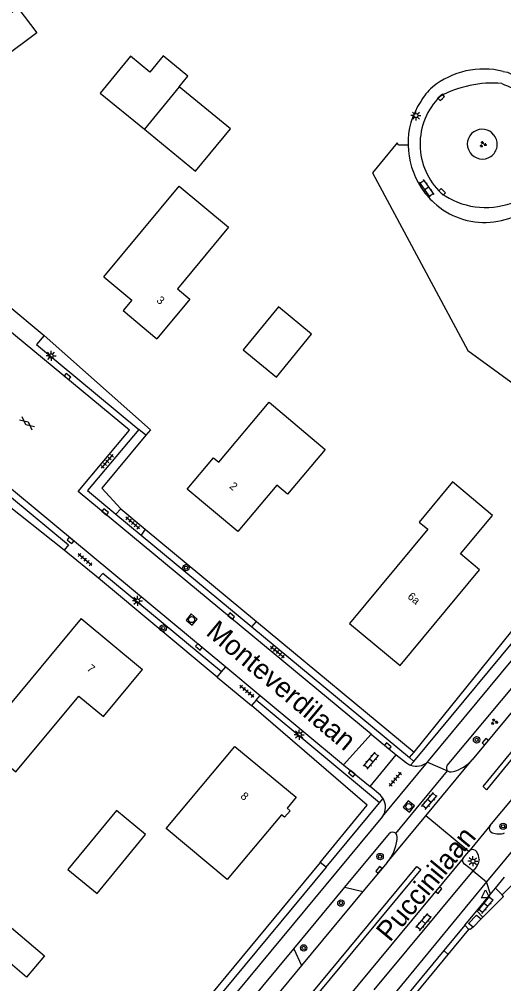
# Model space of a CAD drawing. Extents: x 137999 to 141000, y 397500 to 400501.
# Drawn here: x 138186.2 to 138246.7, y 398870.5 to 398990.9 of the extents above; entities that cross this region are included whole.
import ezdxf

# ---------------------------------------------------------------- set-up
doc = ezdxf.new("R2010")
doc.units = 0
for name, color, linetype in [('gg-afsc-erfafscheiding', 7, 'Continuous'), ('gg-afsc-hekwerk', 7, 'Continuous'), ('gg-anno-huisnummerreeks BGT', 7, 'Continuous'), ('gg-anno-openbare ruimte label', 7, 'Continuous'), ('gg-bbg-gedigitaliseerde bebouwing', 7, 'Continuous'), ('gg-bbg-gedigitaliseerde bijgebouw', 7, 'Continuous'), ('gg-bbg-hoofdgebouw', 7, 'Continuous'), ('gg-bbg-luifel en loopbrug', 7, 'Continuous'), ('gg-bbg-tussenscheiding', 7, 'Continuous'), ('gg-knt-verharding', 7, 'Continuous'), ('gg-knt-verharding nz', 7, 'Continuous'), ('gt-grn-groengrens', 7, 'Continuous'), ('gt-grn-weggrens', 7, 'Continuous'), ('gt-symb-boom', 7, 'Continuous'), ('gt-symb-gesloten verharding', 7, 'Continuous'), ('gt-symb-groenvak', 7, 'Continuous'), ('gt-symb-klinker verharding', 7, 'Continuous'), ('gt-symb-kolk', 7, 'Continuous'), ('gt-symb-lichtmast', 7, 'Continuous'), ('gt-symb-rioolschacht', 7, 'Continuous'), ('gt-symb-tegel verharding', 7, 'Continuous'), ('gt-symb-waterafsluiter', 7, 'Continuous')]:
    doc.layers.add(name, color=color, linetype=linetype)

# ---------------------------------------------------------------- blocks, each defined once
blk = doc.blocks.new('gt0-GESVH1')
at = {"layer": 'gt-symb-gesloten verharding'}
for p, q in [((-0.99, -0.26), (0.01, 0.24)), ((0.01, -0.26), (-0.99, 0.24)), ((0.01, 0.24), (1.01, -0.26)), ((1.01, 0.24), (0.01, -0.26))]:
    blk.add_line(p, q, dxfattribs=at)
blk = doc.blocks.new('gt0-GRVAK')
at = {"layer": 'gt-symb-groenvak'}
for p, q in [((-0.11, 0.19), (-0.23, 0.24)), ((-0.18, 0.15), (0.09, 0.15)), ((-0.09, 0.21), (-0.16, 0.32)), ((-0.05, 0.21), (-0.05, 0.39)), ((0, 0.21), (0.06, 0.32)), ((0.02, 0.19), (0.13, 0.24)), ((0.26, -0.05), (0.2, 0.06)), ((0.31, -0.05), (0.31, 0.13)), ((0.35, -0.05), (0.41, 0.06)), ((-0.24, -0.23), (-0.36, -0.18)), ((-0.32, -0.26), (-0.05, -0.26)), ((-0.23, -0.21), (-0.29, -0.09)), ((-0.18, -0.2), (-0.18, -0.02)), ((-0.14, -0.21), (-0.07, -0.09)), ((-0.12, -0.23), (0, -0.18)), ((0.24, -0.07), (0.12, -0.02)), ((0.17, -0.11), (0.44, -0.11)), ((0.37, -0.07), (0.49, -0.02))]:
    blk.add_line(p, q, dxfattribs=at)
blk = doc.blocks.new('gt0-LMAST')
at = {"layer": 'gt-symb-lichtmast'}
for p, q in [((-0.18, 0.17), (-0.45, 0.44)), ((0, 0.25), (0, 0.62)), ((0.17, 0.17), (0.44, 0.44)), ((-0.25, 0), (-0.63, 0)), ((-0.18, -0.18), (-0.45, -0.45)), ((0, -0.25), (0, -0.63)), ((0.44, -0.45), (0.17, -0.18)), ((0.25, 0), (0.62, 0))]:
    blk.add_line(p, q, dxfattribs=at)
blk.add_circle((0, 0), 0.25, dxfattribs=at)
blk = doc.blocks.new('gt0-KOLK')
at = {"layer": 'gt-symb-kolk'}
blk.add_lwpolyline([(0, 0), (0.37, 0), (0.37, 0.4), (-0.38, 0.4), (-0.38, 0), (0, 0)], dxfattribs=at)
blk = doc.blocks.new('gt0-TEG1')
at = {"layer": 'gt-symb-tegel verharding'}
for p, q in [((-1.13, 0), (1.12, 0)), ((-0.9, -0.25), (-0.9, 0.25)), ((-0.45, -0.25), (-0.45, 0.25)), ((0, -0.25), (0, 0.25)), ((0.45, -0.25), (0.45, 0.25)), ((0.9, -0.25), (0.9, 0.25))]:
    blk.add_line(p, q, dxfattribs=at)
blk = doc.blocks.new('gt0-KL1')
at = {"layer": 'gt-symb-klinker verharding'}
for p, q in [((-1.15, 0.3), (1.15, 0.3)), ((-1, -0.3), (-1, 0.3)), ((-0.5, 0.3), (-0.5, 0.45)), ((0, -0.3), (0, 0.3)), ((0.5, 0.3), (0.5, 0.45)), ((1, -0.3), (1, 0.3)), ((-1.15, -0.3), (1.15, -0.3)), ((-0.5, -0.45), (-0.5, -0.3)), ((0.5, -0.45), (0.5, -0.3))]:
    blk.add_line(p, q, dxfattribs=at)
blk = doc.blocks.new('gt0-BOOM')
at = {"layer": 'gt-symb-boom'}
for radius in [0.4, 0.2]:
    blk.add_circle((0, 0), radius, dxfattribs=at)
blk = doc.blocks.new('gt0-RS')
at = {"layer": 'gt-symb-rioolschacht'}
blk.add_lwpolyline([(-0.5, -0.5), (0.5, -0.5), (0.5, 0.5), (-0.5, 0.5)], close=True, dxfattribs=at)
blk.add_circle((0, 0), 0.375, dxfattribs=at)
blk = doc.blocks.new('gt0-WAFSL')
at = {"layer": 'gt-symb-waterafsluiter'}
for p, q in [((-0.5, -0.33), (0, 0.67)), ((0, 0.67), (0.5, -0.33)), ((0.5, -0.33), (-0.5, -0.33))]:
    blk.add_line(p, q, dxfattribs=at)

msp = doc.modelspace()

# ---------------------------------------------------------------- linework, layer by layer
at = {"layer": 'gg-afsc-erfafscheiding'}
for p, q in [((138191.79, 398924.63), (138177.18, 398936.12)), ((138201.88, 398927.27), (138215.79, 398915.74)), ((138210.88, 398908.8), (138196.05, 398921.16)), ((138235.48, 398899.42), (138249.66, 398916.99)), ((138215.79, 398915.74), (138235.48, 398899.42)), ((138224.5, 398885.05), (138223.75, 398885.64)), ((138242.85, 398877.56), (138243.88, 398878.61)), ((138242.41, 398877.36), (138242.51, 398877.26))]:
    msp.add_line(p, q, dxfattribs=at)
for points in [[(138189.29, 398951.45), (138202.54, 398939.67), (138201.99, 398939.01)], [(138201.99, 398939.01), (138196.46, 398932.4), (138198.84, 398929.79)], [(138223.75, 398885.64), (138229.63, 398892.8), (138215.19, 398905.23)]]:
    msp.add_lwpolyline(points, dxfattribs=at)
at = {"layer": 'gg-afsc-hekwerk'}
for p, q in [((138239.74, 398874.14), (138242.33, 398877.26)), ((138242.33, 398877.26), (138242.41, 398877.36)), ((138227.78, 398859.71), (138239.74, 398874.14))]:
    msp.add_line(p, q, dxfattribs=at)
msp.add_lwpolyline([(138246.62, 398984.43), (138247.15, 398984.34), (138247.64, 398984.1)], dxfattribs=at)
for centre, radius, start, end in [((138244.19, 398974.53), 10.2, 76.26, 128.9473), ((138241.66, 398977.8), 6.06, 129.8009, 151.9732), ((138244.01, 398975.47), 9.28, 146.0446, 181.5217)]:
    msp.add_arc(centre, radius, start, end, dxfattribs=at)
at = {"layer": 'gg-bbg-gedigitaliseerde bebouwing'}
for points in [[(138196.73, 398958.76), (138206.15, 398970.09), (138212.31, 398964.99), (138205.93, 398957.27), (138207.48, 398955.99), (138203.35, 398951.05)], [(138210.44, 398936.19), (138211.09, 398935.64), (138217.39, 398943.12), (138224.4, 398937.22), (138219.69, 398931.62)], [(138193.9, 398916.11), (138181.16, 398900.78), (138185.74, 398896.98), (138193.59, 398906.42), (138196.68, 398903.86), (138201.56, 398909.74)], [(138218.91, 398891.61), (138212.15, 398883.5), (138204.52, 398889.87)]]:
    msp.add_lwpolyline(points, dxfattribs=at)
at = {"layer": 'gg-bbg-gedigitaliseerde bijgebouw'}
for points in [[(138206.16, 398982.52), (138207.24, 398983.85), (138204.15, 398986.38), (138202.47, 398984.33), (138200.05, 398986.32), (138196.29, 398981.73), (138201.81, 398977.2)], [(138201.81, 398977.2), (138208.2, 398971.96), (138212.56, 398977.27), (138206.16, 398982.52)], [(138214.14, 398949.66), (138218.28, 398946.26), (138222.67, 398951.61), (138218.53, 398955.01), (138214.14, 398949.66)], [(138192.25, 398884.75), (138195.89, 398881.76), (138201.94, 398889.13), (138198.3, 398892.12), (138192.25, 398884.75)]]:
    msp.add_lwpolyline(points, dxfattribs=at)
at = {"layer": 'gg-bbg-hoofdgebouw'}
msp.add_line((138193.9, 398916.11), (138201.56, 398909.74), dxfattribs=at)
for points in [[(138196.73, 398958.76), (138200.21, 398955.88), (138199.13, 398954.58), (138203.35, 398951.05)], [(138219.69, 398931.62), (138218.34, 398932.75), (138213.47, 398926.96), (138207.15, 398932.28), (138210.44, 398936.19)], [(138227.41, 398915.5), (138233.74, 398910.24), (138243.68, 398922.18), (138241.3, 398924.17), (138245.3, 398928.99), (138240.28, 398933.16), (138236.11, 398928.15), (138237.19, 398927.25), (138227.41, 398915.5)], [(138204.52, 398889.87), (138213.08, 398900.14), (138220.75, 398893.79), (138219.62, 398892.43), (138220, 398892.11), (138219.3, 398891.29), (138218.91, 398891.61)]]:
    msp.add_lwpolyline(points, dxfattribs=at)
at = {"layer": 'gg-bbg-luifel en loopbrug'}
for points in [[(138182.56, 398988.08), (138183.52, 398988.8), (138182.68, 398989.92), (138186, 398992.39), (138188.35, 398989.23), (138184.07, 398986.05)], [(138184.89, 398877.73), (138189.33, 398874), (138187.08, 398871.32), (138182.64, 398875.05), (138184.89, 398877.73)]]:
    msp.add_lwpolyline(points, dxfattribs=at)
at = {"layer": 'gg-bbg-tussenscheiding'}
msp.add_line((138206.16, 398982.52), (138201.81, 398977.2), dxfattribs=at)
at = {"layer": 'gg-knt-verharding'}
for p, q in [((138245.51, 398976.43), (138245.46, 398976.49)), ((138178.54, 398937.75), (138211.95, 398910.06)), ((138198.24, 398929.14), (138198.84, 398929.79)), ((138198.84, 398929.79), (138201.88, 398927.27)), ((138198.24, 398929.14), (138201.41, 398926.51)), ((138201.88, 398927.27), (138201.41, 398926.51)), ((138201.41, 398926.51), (138215.21, 398915.06)), ((138196.05, 398921.16), (138191.79, 398924.63)), ((138235.46, 398898.27), (138250.45, 398916.35)), ((138215.21, 398915.06), (138234.91, 398898.73)), ((138237.3, 398898.34), (138251.51, 398915.49)), ((138211.44, 398909.46), (138211.95, 398910.06)), ((138211.95, 398910.06), (138216.24, 398906.5)), ((138210.88, 398908.8), (138211.44, 398909.46)), ((138239.64, 398897.76), (138248.73, 398908.64)), ((138215.74, 398905.9), (138216.24, 398906.5)), ((138216.24, 398906.5), (138226.68, 398897.85)), ((138215.74, 398905.9), (138215.19, 398905.23)), ((138231.18, 398893.09), (138215.74, 398905.9)), ((138248.39, 398905.28), (138242.75, 398898.44)), ((138226.68, 398897.85), (138230.11, 398901.68)), ((138230.11, 398901.68), (138233.25, 398899.08)), ((138244.97, 398890.23), (138252.82, 398899.64)), ((138230.02, 398895.12), (138233.25, 398899.08)), ((138231.56, 398891.4), (138237.15, 398898.16)), ((138234.91, 398898.73), (138235.46, 398898.27)), ((138236.96, 398891.48), (138242.75, 398898.44)), ((138237.15, 398898.16), (138237.3, 398898.34)), ((138226.68, 398897.85), (138230.02, 398895.12)), ((138233.19, 398889.28), (138239.68, 398897.07)), ((138224.5, 398885.05), (138231.18, 398893.09)), ((138253.45, 398893.99), (138244.54, 398883.21)), ((138231.56, 398891.4), (138180.34, 398829.77)), ((138232.12, 398885.63), (138236.96, 398891.48)), ((138245, 398889.54), (138245.25, 398889.36)), ((138226.84, 398882.55), (138232.4, 398889.24)), ((138241.6, 398886.16), (138227.3, 398868.9)), ((138241.6, 398886.16), (138242.32, 398887.03)), ((138224.5, 398885.05), (138204.87, 398861.42)), ((138232.12, 398885.63), (138229.1, 398882)), ((138243.25, 398885.07), (138242.86, 398884.6)), ((138230.52, 398869.74), (138242.86, 398884.6)), ((138245.65, 398882.44), (138246.77, 398883.79)), ((138244.54, 398883.21), (138194.3, 398822.37)), ((138220.45, 398874.86), (138226.84, 398882.55)), ((138245.02, 398881.68), (138245.65, 398882.44)), ((138245.65, 398882.44), (138246.48, 398881.59)), ((138229.1, 398882), (138221.43, 398872.77)), ((138243.31, 398879.61), (138245.02, 398881.68)), ((138241.82, 398877.82), (138243.31, 398879.61)), ((138243.31, 398879.61), (138244.08, 398878.81)), ((138241.82, 398877.82), (138239.19, 398874.65)), ((138241.82, 398877.82), (138242.33, 398877.26)), ((138182.57, 398829.28), (138220.45, 398874.86)), ((138239.19, 398874.65), (138227.21, 398860.19)), ((138239.19, 398874.65), (138239.74, 398874.14)), ((138221.43, 398872.77), (138185.99, 398830.13))]:
    msp.add_line(p, q, dxfattribs=at)
for points in [[(138180.43, 398950.76), (138184.47, 398955.46), (138189.29, 398951.45)], [(138230.11, 398901.68), (138193.51, 398931.97), (138199.95, 398939.63), (138184.49, 398952.41), (138176.73, 398943.21)], [(138189.29, 398951.45), (138188.32, 398950.32), (138201.1, 398939.73)], [(138201.1, 398939.73), (138194.68, 398932.09), (138198.24, 398929.14)], [(138178.04, 398937.15), (138192.33, 398925.3), (138191.79, 398924.63)], [(138211.44, 398909.46), (138196.62, 398921.74), (138196.05, 398921.16)], [(138244.54, 398894.73), (138244.1, 398895.14), (138251.05, 398903.54), (138251.5, 398903.19), (138244.54, 398894.73)], [(138239.68, 398897.07), (138239.9, 398896.95), (138240.13, 398896.95), (138240.36, 398897)], [(138246.48, 398881.59), (138261.32, 398896.39), (138272.53, 398884.92)], [(138233.38, 398888.51), (138233.39, 398888.82), (138233.34, 398889.08), (138233.19, 398889.28)], [(138243.61, 398886), (138243.53, 398886.51), (138243.31, 398886.98), (138243.16, 398887.12), (138242.97, 398887.22), (138242.75, 398887.25), (138242.51, 398887.18), (138242.32, 398887.03)], [(138242.86, 398884.6), (138241.79, 398885.44), (138241.61, 398885.65), (138241.55, 398885.91), (138241.6, 398886.16)], [(138243.61, 398886), (138243.49, 398885.51), (138243.25, 398885.07)], [(138188.2, 398826.72), (138187.74, 398827.1), (138235.82, 398885.14), (138236.32, 398884.78), (138188.2, 398826.72)], [(138244.08, 398878.81), (138246.66, 398881.4), (138246.48, 398881.59)]]:
    msp.add_lwpolyline(points, dxfattribs=at)
for centre, radius, start, end in [((138244.01, 398975.34), 1.87, 123.8063, 212.7144), ((138244.01, 398975.38), 1.83, 37.2793, 124.5958), ((138244.03, 398975.32), 1.85, 304.7797, 36.7073), ((138244.76, 398975.41), 10.02, 181.0968, 212.8815), ((138244.03, 398975.39), 1.91, 213.9708, 303.7681), ((138244.75, 398975.41), 10.02, 212.8838, 227.3107), ((138244.31, 398974.96), 9.39, 227.4072, 320.8393), ((138239.11, 398901.76), 4.92, 284.645, 317.6344), ((138240.02, 398897.43), 0.5, 140.168, 227.3164), ((138245.49, 398889.91), 0.61, 147.6601, 217.1256), ((138227.46, 398889.39), 5.99, 321.078, 351.5004), ((138232.82, 398888.84), 0.577, 49.8742, 135.8142), ((138246.06, 398891.33), 2.13, 247.5596, 290.1459)]:
    msp.add_arc(centre, radius, start, end, dxfattribs=at)
at = {"layer": 'gg-knt-verharding nz'}
for p, q in [((138210.88, 398908.8), (138215.19, 398905.23)), ((138233.25, 398899.08), (138234.52, 398898.08)), ((138231.28, 398894.04), (138230.02, 398895.12)), ((138244.97, 398890.23), (138242.32, 398887.03))]:
    msp.add_line(p, q, dxfattribs=at)
for centre, radius, start, end in [((138245.38, 398968.87), 14.11, 85.6679, 118.1341), ((138250.52, 398990.68), 8.75, 242.2475, 282.1487), ((138244.61, 398975.34), 8.38, 134.5714, 226.8226), ((138244.43, 398976.91), 9.48, 234.1222, 289.8826), ((138235.79, 398899.76), 2.11, 233.1567, 249.8614), ((138235.78, 398899.76), 2.1, 249.9066, 310.6646), ((138229.82, 398892.54), 2.09, 30.8236, 45.7044), ((138229.83, 398892.55), 2.08, 326.3655, 30.7419)]:
    msp.add_arc(centre, radius, start, end, dxfattribs=at)
at = {"layer": 'gt-grn-groengrens'}
for p, q in [((138201.99, 398939.01), (138201.1, 398939.73)), ((138215.21, 398915.06), (138215.79, 398915.74)), ((138234.91, 398898.73), (138235.48, 398899.42)), ((138226.84, 398882.55), (138229.1, 398882)), ((138243.88, 398878.61), (138244.08, 398878.81)), ((138242.85, 398877.56), (138242.51, 398877.26)), ((138220.45, 398874.86), (138221.43, 398872.77))]:
    msp.add_line(p, q, dxfattribs=at)
for points in [[(138234.73, 398975.22), (138233.55, 398975.22), (138233.39, 398975.52), (138230.31, 398971.78), (138242.21, 398949.56), (138249.87, 398943.99), (138250.82, 398942.5), (138250.61, 398936.37), (138253.23, 398931.63)], [(138223.75, 398885.64), (138204.17, 398862), (138204.87, 398861.42)], [(138242.85, 398877.56), (138242.3, 398878), (138243.27, 398879.08), (138243.88, 398878.61)]]:
    msp.add_lwpolyline(points, dxfattribs=at)
at = {"layer": 'gt-grn-weggrens'}
for p, q in [((138235.06, 398897.78), (138235.46, 398898.27)), ((138237.15, 398898.16), (138239.68, 398897.07)), ((138231.18, 398893.09), (138231.62, 398893.62)), ((138242.32, 398887.03), (138236.96, 398891.48)), ((138242.86, 398884.6), (138244.54, 398883.21)), ((138245.02, 398881.68), (138244.54, 398883.21))]:
    msp.add_line(p, q, dxfattribs=at)

# ---------------------------------------------------------------- block references
at = {"layer": 'gt-symb-boom'}
for p in [(138206.99, 398922.46), (138204.15, 398914.91), (138243.3, 398900.96), (138246.61, 398890.15), (138231.24, 398886.38), (138226.35, 398880.57), (138221.7, 398874.97)]:
    msp.add_blockref('gt0-BOOM', p, dxfattribs=at)
at = {"layer": 'gt-symb-gesloten verharding', "rotation": -38.990994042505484}
msp.add_blockref('gt0-GESVH1', (138187.13, 398940.5), dxfattribs=at)
at = {"layer": 'gt-symb-groenvak'}
for p in [(138244.09, 398975.32), (138245.5, 398903.21)]:
    msp.add_blockref('gt0-GRVAK', p, dxfattribs=at)
at = {"layer": 'gt-symb-klinker verharding'}
for p, rotation in [((138237.04, 398969.83), -55.30847117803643), ((138230.13, 398898.36), 49.98904227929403), ((138237.4, 398893.32), 49.98904227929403), ((138244.46, 398880.34), 50.15042857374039), ((138236.69, 398878.19), 49.98904227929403)]:
    msp.add_blockref('gt0-KL1', p, dxfattribs=dict(at, rotation=rotation))
at = {"layer": 'gt-symb-kolk'}
for p, rotation in [((138239.02, 398981.05), 41.99999127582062), ((138239.14, 398969.54), 136.0534104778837), ((138192.05, 398946.16), -39.563508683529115), ((138196.78, 398929.27), -39.644174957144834), ((138192.45, 398925.7), -39.644174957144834), ((138212.5, 398916.25), -39.644174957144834), ((138208.49, 398912.41), -39.644174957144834), ((138232.1, 398900.03), -39.644174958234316), ((138244.53, 398900.6), 50.436491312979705), ((138227.59, 398896.58), -39.644174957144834), ((138231.25, 398884.59), 50.4364913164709), ((138238.72, 398882.06), 50.35582504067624)]:
    msp.add_blockref('gt0-KOLK', p, dxfattribs=dict(at, rotation=rotation))
at = {"layer": 'gt-symb-lichtmast'}
for p in [(138235.72, 398978.92), (138190.14, 398948.91), (138200.93, 398918.3), (138221.14, 398901.6), (138242.84, 398885.79)]:
    msp.add_blockref('gt0-LMAST', p, dxfattribs=at)
at = {"layer": 'gt-symb-rioolschacht'}
for p, rotation in [((138207.7, 398915.97), -39.644174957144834), ((138234.83, 398892.63), 50.35582504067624)]:
    msp.add_blockref('gt0-RS', p, dxfattribs=dict(at, rotation=rotation))
at = {"layer": 'gt-symb-tegel verharding'}
for p, rotation in [((138197.17, 398935.73), 49.98904227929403), ((138200.34, 398928.04), 139.98904227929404), ((138194.38, 398923.46), 139.98904228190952), ((138218.4, 398911.91), 139.98904227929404), ((138214.59, 398907.03), 139.98904227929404), ((138233.14, 398896.04), 49.98904228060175)]:
    msp.add_blockref('gt0-TEG1', p, dxfattribs=dict(at, rotation=rotation))
at = {"layer": 'gt-symb-waterafsluiter'}
msp.add_blockref('gt0-WAFSL', (138244.43, 398881.55), dxfattribs=at)

# ---------------------------------------------------------------- texts
at = {"layer": 'gg-anno-huisnummerreeks BGT'}
for s, rotation, p in [('3', 320.1, (138203.23, 398955.71)), ('2', 319.9, (138212.34, 398932.49)), ('6a', 320.2, (138234.59, 398918.72)), ('7', 320.3, (138194.54, 398909.72)), ('8', 320.4, (138213.72, 398893.77))]:
    msp.add_text(s, height=1, rotation=rotation, dxfattribs=at).set_placement(p)
at = {"layer": 'gg-anno-openbare ruimte label'}
for s, rotation, p in [('Monteverdilaan', 320, (138209.36, 398914.16)), ('Puccinilaan', 50.4, (138232.47, 398875.61))]:
    msp.add_text(s, height=2.5, rotation=rotation, dxfattribs=at).set_placement(p)

doc.saveas('drawing.dxf')
